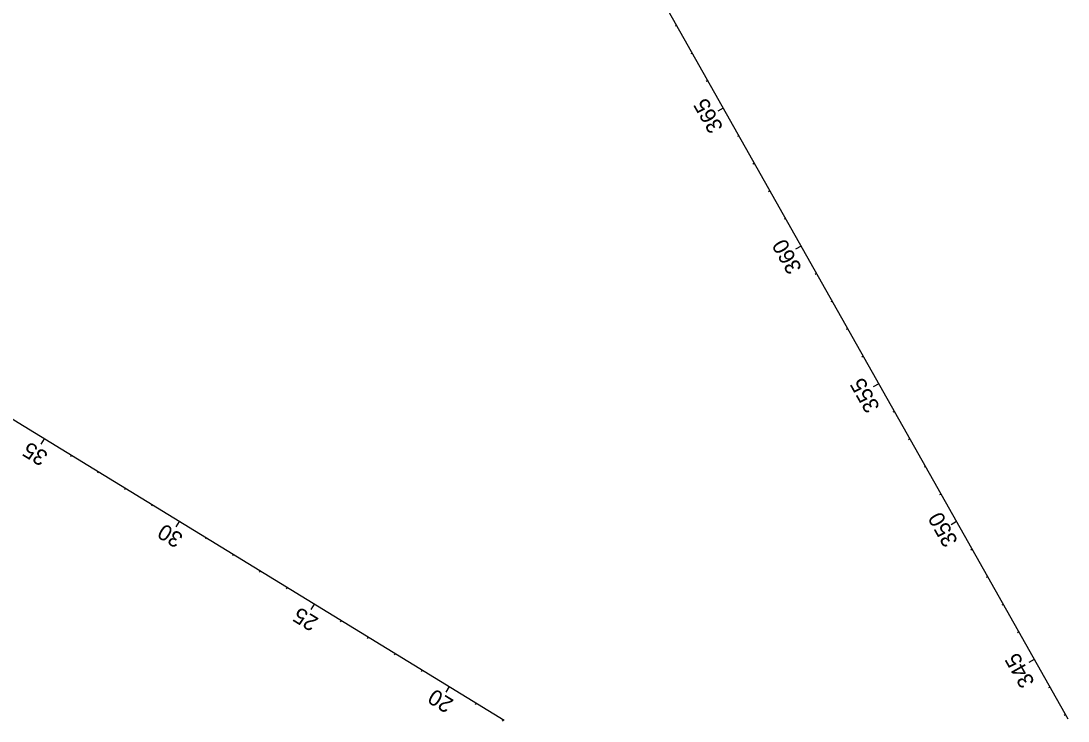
# Model space of a CAD drawing. Extents: x 448091 to 665917, y 1461380 to 1587607.
# Drawn here: x 509419 to 512728, y 1560400 to 1562612 of the extents above; entities that cross this region are included whole.
import ezdxf

# ---------------------------------------------------------------- set-up
doc = ezdxf.new("R2010")
doc.units = 0
doc.layers.add('TextShtNo', color=7, linetype='Continuous')
doc.layers.add('TextTitle', color=7, linetype='Continuous')

msp = doc.modelspace()

# ---------------------------------------------------------------- linework, layer by layer
at = {"layer": 'TextShtNo'}
for p, q in [((512728.1, 1560405.4), (509715.2, 1565743)), ((510946.2, 1560401.8), (509342.9, 1561383))]:
    msp.add_line(p, q, dxfattribs=at)
at = {"layer": 'TextTitle'}
for p, q in [((511490.9, 1562597.2), (511486.6, 1562594.7)), ((511540.1, 1562510.1), (511535.7, 1562507.6)), ((511589.2, 1562423), (511584.9, 1562420.6)), ((511638.4, 1562335.9), (511621, 1562326.1)), ((511687.6, 1562248.8), (511683.2, 1562246.4)), ((511736.7, 1562161.8), (511732.4, 1562159.3)), ((511785.9, 1562074.7), (511781.5, 1562072.2)), ((511835, 1561987.6), (511830.7, 1561985.1)), ((511884.2, 1561900.5), (511866.8, 1561890.7)), ((511933.3, 1561813.4), (511929, 1561811)), ((511982.5, 1561726.3), (511978.1, 1561723.9)), ((512031.6, 1561639.3), (512027.3, 1561636.8)), ((512080.8, 1561552.2), (512076.5, 1561549.7)), ((512130, 1561465.1), (512112.5, 1561455.3)), ((512179.1, 1561378), (512174.8, 1561375.5)), ((509492.6, 1561291.4), (509482.2, 1561274.4)), ((512228.3, 1561290.9), (512223.9, 1561288.5)), ((509577.9, 1561239.2), (509575.3, 1561235)), ((509663.2, 1561187), (509660.6, 1561182.8)), ((512277.4, 1561203.8), (512273.1, 1561201.4)), ((509748.5, 1561134.8), (509745.9, 1561130.6)), ((512326.6, 1561116.7), (512322.2, 1561114.3)), ((509833.8, 1561082.6), (509831.2, 1561078.4)), ((509919.1, 1561030.4), (509908.6, 1561013.4)), ((512375.7, 1561029.7), (512358.3, 1561019.8)), ((510004.4, 1560978.2), (510001.8, 1560974)), ((512424.9, 1560942.6), (512420.5, 1560940.1)), ((510089.7, 1560926), (510087.1, 1560921.8)), ((510175, 1560873.8), (510172.3, 1560869.6)), ((512474.1, 1560855.5), (512469.7, 1560853)), ((510260.3, 1560821.6), (510257.6, 1560817.4)), ((510345.5, 1560769.4), (510335.1, 1560752.4)), ((512523.2, 1560768.4), (512518.9, 1560766)), ((510430.8, 1560717.2), (510428.2, 1560712.9)), ((512572.4, 1560681.3), (512568, 1560678.9)), ((510516.1, 1560665), (510513.5, 1560660.7)), ((510601.4, 1560612.8), (510598.8, 1560608.5)), ((512621.5, 1560594.2), (512604.1, 1560584.4)), ((510686.7, 1560560.6), (510684.1, 1560556.3)), ((510772, 1560508.4), (510761.6, 1560491.3)), ((512670.7, 1560507.2), (512666.3, 1560504.7)), ((510857.3, 1560456.2), (510854.7, 1560451.9)), ((512719.8, 1560420.1), (512715.5, 1560417.6)), ((510942.6, 1560404), (510940, 1560399.7))]:
    msp.add_line(p, q, dxfattribs=at)

# ---------------------------------------------------------------- texts
for s, rotation, p in [('365', 119.4433, (511639.9, 1562275.1)), ('360', 119.4433, (511888.5, 1561830.3)), ('355', 119.4433, (512134.9, 1561391.9)), ('35', 148.5322, (509508.1, 1561245.3)), ('350', 119.4433, (512381.5, 1560968.1)), ('30', 148.5322, (509935.1, 1560986.6)), ('25', 148.5322, (510362.6, 1560722.8)), ('345', 119.4433, (512624, 1560522.6)), ('20', 148.5322, (510789.5, 1560464.8))]:
    msp.add_text(s, height=50, rotation=rotation, dxfattribs=at).set_placement(p)

doc.saveas('drawing.dxf')
